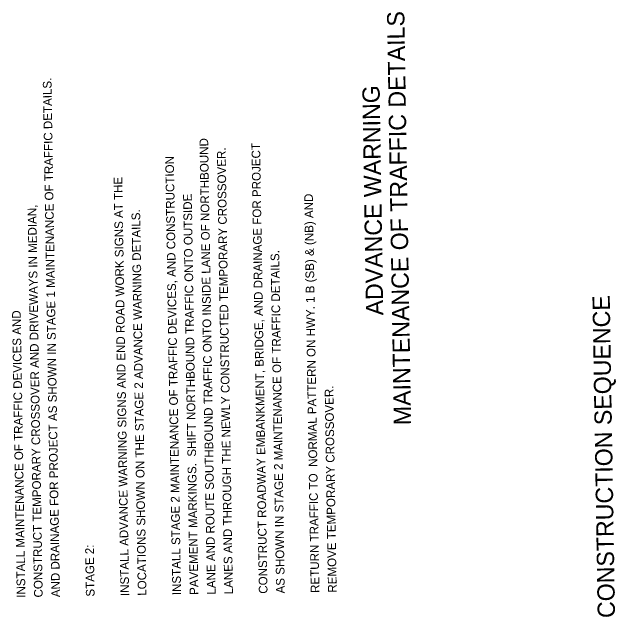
# Model space of a CAD drawing. Extents: x 1676063 to 1678026, y 228339 to 229904.
# Drawn here: x 1677606.6 to 1678025.6, y 229485 to 229904.2 of the extents above; entities that cross this region are included whole.
import ezdxf

# ---------------------------------------------------------------- set-up
doc = ezdxf.new("R2010")
doc.units = 0
doc.layers.add('R_Annotation', color=7, linetype='Continuous')

msp = doc.modelspace()

# ---------------------------------------------------------------- texts
at = {"layer": 'R_Annotation'}
for s, height, p in [('MAINTENANCE OF TRAFFIC DETAILS', 12, (1677883.51, 229617.96)), ('AND DRAINAGE FOR PROJECT AS SHOWN IN STAGE 1 MAINTENANCE OF TRAFFIC DETAILS. ', 6, (1677639.9, 229498.67)), ('ADVANCE WARNING', 12, (1677864.25, 229694.05)), ('LANE AND ROUTE SOUTHBOUND TRAFFIC ONTO INSIDE LANE OF NORTHBOUND ', 6, (1677747.88, 229500.46)), ('CONSTRUCT ROADWAY EMBANKMENT, BRIDGE, AND DRAINAGE FOR PROJECT ', 6, (1677783.88, 229501.06)), ('LANES AND THROUGH THE NEWLY CONSTRUCTED TEMPORARY CROSSOVER. ', 6, (1677759.88, 229500.66)), ('INSTALL STAGE 2 MAINTENANCE OF TRAFFIC DEVICES, AND CONSTRUCTION ', 6, (1677723.89, 229500.06)), ('INSTALL ADVANCE WARNING SIGNS AND END ROAD WORK SIGNS AT THE', 6, (1677687.89, 229499.46)), ('PAVEMENT MARKINGS.  SHIFT NORTHBOUND TRAFFIC ONTO OUTSIDE ', 6, (1677735.89, 229500.26)), ('RETURN TRAFFIC TO  NORMAL PATTERN ON HWY. 1 B (SB) & (NB) AND', 6, (1677819.88, 229501.65)), ('CONSTRUCT TEMPORARY CROSSOVER AND DRIVEWAYS IN MEDIAN, ', 6, (1677627.9, 229498.47)), ('LOCATIONS SHOWN ON THE STAGE 2 ADVANCE WARNING DETAILS.  ', 6, (1677699.89, 229499.66)), ('AS SHOWN IN STAGE 2 MAINTENANCE OF TRAFFIC DETAILS.', 6, (1677795.88, 229501.25)), ('CONSTRUCTION SEQUENCE', 12, (1678025, 229484.28)), ('INSTALL MAINTENANCE OF TRAFFIC DEVICES AND ', 6, (1677615.9, 229498.27)), ('REMOVE TEMPORARY CROSSOVER.', 6, (1677831.87, 229501.85)), ('STAGE 2:', 6, (1677663.9, 229499.07))]:
    msp.add_text(s, height=height, rotation=90.9497, dxfattribs=at).set_placement(p)

doc.saveas('drawing.dxf')
